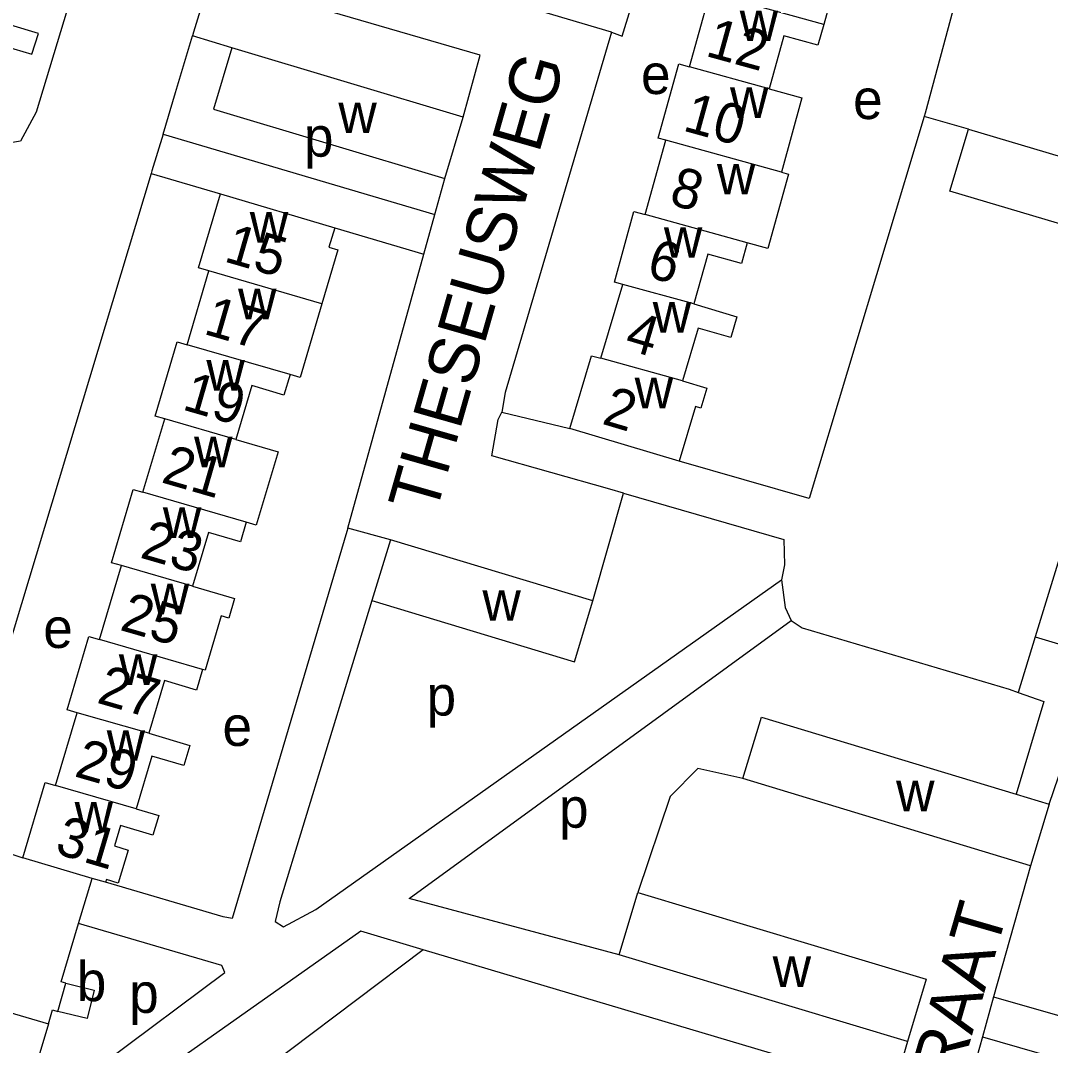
# Model space of a CAD drawing. Extents: x 161773 to 163836, y 384796 to 386521.
# Drawn here: x 162680 to 162783.7, y 386020.7 to 386123.9 of the extents above; entities that cross this region are included whole.
import ezdxf

# ---------------------------------------------------------------- set-up
doc = ezdxf.new("R2010")
doc.units = 0
for name, color, linetype in [('BLT_Basislijn', 7, 'Continuous'), ('BLT_Bebouwing', 7, 'Continuous'), ('BLT_Centroide', 7, 'Continuous'), ('BLT_Huisnummer', 7, 'Continuous'), ('BLT_Huisnummer_ tussenligend', 7, 'Continuous'), ('BLT_Onderverdeling_panden', 7, 'Continuous'), ('BLT_Straatnaam', 7, 'Continuous')]:
    doc.layers.add(name, color=color, linetype=linetype)

msp = doc.modelspace()

# ---------------------------------------------------------------- linework, layer by layer
at = {"layer": 'BLT_Basislijn'}
for p, q in [((162739.49, 386122.72), (162727.31, 386126.36)), ((162701.29, 386121.17), (162697.31, 386122.36)), ((162775.44, 386112.96), (162770.97, 386114.22)), ((162694.37, 386112.46), (162721.71, 386104.35)), ((162693.17, 386108.5), (162700.14, 386106.43)), ((162721.71, 386104.35), (162722.72, 386107.98)), ((162720.61, 386100.37), (162721.71, 386104.35)), ((162711.64, 386103.01), (162720.61, 386100.37)), ((162712.95, 386072.76), (162720.61, 386100.37)), ((162728.46, 386084.46), (162735.3, 386082.8)), ((162737.62, 386065.43), (162740.72, 386076.3)), ((162786.6, 386076.33), (162782.17, 386061.82)), ((162717.24, 386071.6), (162712.95, 386072.76)), ((162782.17, 386061.82), (162780.46, 386056.21)), ((162781.69, 386038.75), (162777.98, 386025.55)), ((162685.84, 386032.93), (162687.21, 386037.49)), ((162767.88, 386016.22), (162720.55, 386030.29)), ((162777.98, 386025.55), (162776.85, 386021.54)), ((162777.98, 386025.55), (162816.59, 386014.4)), ((162776.85, 386021.54), (162767.14, 385986.96)), ((162776.85, 386021.54), (162814.38, 386010.7)), ((162769.31, 386021.06), (162767.88, 386016.22))]:
    msp.add_line(p, q, dxfattribs=at)
for points in [[(162697.19, 386166.25), (162681.58, 386114.67), (162679.99, 386111.76), (162677.03, 386111.25), (162656.86, 386117.36)], [(162739.49, 386122.72), (162740.58, 386122.32), (162749.41, 386150.96)], [(162778.62, 386142.65), (162771.08, 386114.58), (162770.97, 386114.22)], [(162699.14, 386128.34), (162697.43, 386122.74), (162697.31, 386122.36)], [(162724.58, 386114.17), (162726.27, 386120.43), (162699.14, 386128.34)], [(162694.37, 386112.46), (162695.61, 386116.65), (162697.31, 386122.36)], [(162739.49, 386122.72), (162728.8, 386086.45), (162728.46, 386084.46)], [(162770.97, 386114.22), (162759.42, 386075.76), (162746.32, 386079.51)], [(162694.37, 386112.46), (162693.24, 386108.77), (162693.17, 386108.5)], [(162693.17, 386108.5), (162673.85, 386044.54), (162673.88, 386042.3), (162676.01, 386040.97), (162680.25, 386039.55)], [(162740.72, 386076.3), (162739.35, 386076.7), (162727.46, 386080.06), (162728.08, 386083.73), (162728.46, 386084.46)], [(162740.72, 386076.3), (162756.87, 386071.61), (162756.91, 386069.09), (162756.61, 386067.57)], [(162712.95, 386072.76), (162712.86, 386072.42), (162701.32, 386033.46), (162700.4, 386033.6), (162688.57, 386037.09)], [(162715.39, 386065.47), (162706.11, 386035.11), (162705.66, 386033.14), (162706.47, 386032.6), (162709.75, 386034.35), (162756.61, 386067.57)], [(162756.61, 386067.57), (162756.98, 386064.76), (162757.6, 386063.48)], [(162740.27, 386029.79), (162719.12, 386035.47), (162757.6, 386063.48)], [(162757.6, 386063.48), (162758.69, 386062.74), (162779.55, 386056.54), (162780.46, 386056.21)], [(162782.17, 386061.82), (162833.81, 386046.33), (162835.47, 386045.46)], [(162780.46, 386056.21), (162783.02, 386055.3), (162780.26, 386045.96)], [(162783.57, 386044.95), (162786.42, 386053.34), (162788.91, 386054.31), (162791.62, 386054.09), (162832.86, 386041.3)], [(162752.73, 386047.55), (162748.19, 386048.56), (162745.4, 386045.73), (162742.16, 386036.08)], [(162660.47, 386022.67), (162657.67, 386012.8), (162671.37, 386009.02), (162674.33, 386009.21), (162676.46, 386010), (162700.59, 386027.99), (162700.27, 386028.72), (162685.84, 386032.93)], [(162684.56, 386026.93), (162684.09, 386027.08), (162685.84, 386032.93)], [(162720.55, 386030.29), (162714.27, 386032.16), (162682.42, 386009.68), (162682.73, 386007.33), (162683.24, 386006.55), (162696.85, 386003.37)], [(162720.55, 386030.29), (162700.51, 386015.19), (162696.85, 386003.37)], [(162682.81, 386022.83), (162683.24, 386024.25), (162683.76, 386024.09)]]:
    msp.add_lwpolyline(points, dxfattribs=at)
at = {"layer": 'BLT_Bebouwing'}
for p, q in [((162747.37, 386119.24), (162749.43, 386126.68)), ((162724.58, 386114.17), (162701.29, 386121.17)), ((162722.72, 386107.98), (162724.58, 386114.17)), ((162775.44, 386112.96), (162795.86, 386106.88)), ((162742.91, 386104.35), (162744.98, 386111.84)), ((162700.14, 386106.43), (162711.64, 386103.01)), ((162696.77, 386091.25), (162698.97, 386098.68)), ((162738.44, 386089.88), (162740.66, 386097.32)), ((162692.32, 386076.39), (162694.52, 386083.77)), ((162746.32, 386079.51), (162735.3, 386082.8)), ((162717.24, 386071.6), (162715.39, 386065.47)), ((162737.62, 386065.43), (162717.24, 386071.6)), ((162687.97, 386061.55), (162690.17, 386068.99)), ((162683.54, 386046.83), (162685.72, 386054.18)), ((162781.69, 386038.75), (162752.73, 386047.55)), ((162780.26, 386045.96), (162783.57, 386044.95)), ((162783.57, 386044.95), (162781.69, 386038.75)), ((162687.21, 386037.49), (162680.25, 386039.55)), ((162688.57, 386037.09), (162687.21, 386037.49)), ((162740.27, 386029.79), (162742.16, 386036.08)), ((162769.31, 386021.06), (162740.27, 386029.79)), ((162662.33, 386028.92), (162682.81, 386022.83)), ((162683.76, 386024.09), (162684.56, 386026.93))]:
    msp.add_line(p, q, dxfattribs=at)
for points in [[(162762.95, 386131.07), (162760.87, 386123.52)], [(162674.49, 386118.8), (162677.4, 386117.93), (162678.43, 386121.32), (162681.16, 386120.5), (162681.8, 386122.61), (162679.04, 386123.45)], [(162760.87, 386123.52), (162760.29, 386121.42), (162756.86, 386122.37), (162755.39, 386117.02)], [(162701.29, 386121.17), (162699.43, 386114.98), (162722.72, 386107.98)], [(162744.98, 386111.84), (162744.21, 386112.05), (162746.27, 386119.54), (162747.37, 386119.24)], [(162755.39, 386117.02), (162758.68, 386116.12), (162756.61, 386108.63)], [(162794, 386100.64), (162773.58, 386106.72), (162775.44, 386112.96)], [(162756.61, 386108.63), (162757.33, 386108.43), (162755.26, 386100.93), (162753.17, 386101.51)], [(162698.97, 386098.68), (162697.92, 386098.98), (162700.14, 386106.43)], [(162740.66, 386097.32), (162739.81, 386097.55), (162741.77, 386104.66), (162742.91, 386104.35)], [(162711.64, 386103.01), (162711.06, 386101.06), (162711.96, 386100.79), (162710.35, 386095.36)], [(162753.17, 386101.51), (162752.6, 386099.44), (162749.19, 386100.38), (162747.79, 386095.35)], [(162710.35, 386095.36), (162708.15, 386087.94), (162707.14, 386088.24)], [(162747.79, 386095.35), (162752.14, 386094.05), (162751.52, 386091.96), (162748.24, 386092.93), (162746.65, 386087.61)], [(162694.52, 386083.77), (162693.55, 386084.05), (162695.77, 386091.54), (162696.77, 386091.25)], [(162735.3, 386082.8), (162737.48, 386090.14), (162738.44, 386089.88)], [(162707.14, 386088.24), (162706.53, 386086.17), (162703.28, 386087.14), (162701.67, 386081.7)], [(162746.65, 386087.61), (162749.09, 386086.88), (162748.49, 386084.87), (162747.96, 386085.03), (162746.32, 386079.51)], [(162701.67, 386081.7), (162705.93, 386080.44), (162703.74, 386073.06), (162702.74, 386073.36)], [(162690.17, 386068.99), (162689.16, 386069.28), (162691.35, 386076.67), (162692.32, 386076.39)], [(162702.74, 386073.36), (162702.15, 386071.38), (162698.93, 386072.34), (162697.32, 386066.92)], [(162697.32, 386066.92), (162701.56, 386065.67), (162700.97, 386063.69), (162700.2, 386063.92), (162698.58, 386058.45), (162698.34, 386058.53)], [(162715.39, 386065.47), (162735.77, 386059.3), (162737.62, 386065.43)], [(162685.72, 386054.18), (162684.71, 386054.47), (162686.9, 386061.86), (162687.97, 386061.55)], [(162698.34, 386058.53), (162697.73, 386056.45), (162694.49, 386057.41), (162692.91, 386052.1)], [(162752.73, 386047.55), (162754.61, 386053.74), (162780.26, 386045.96)], [(162692.91, 386052.1), (162697.05, 386050.87), (162696.46, 386048.86), (162693.23, 386049.81), (162691.65, 386044.49)], [(162680.25, 386039.55), (162682.49, 386047.14), (162683.54, 386046.83)], [(162691.65, 386044.49), (162693.93, 386043.82), (162693.34, 386041.85), (162690.08, 386042.81), (162689.46, 386040.75), (162690.83, 386040.34), (162689.84, 386037.01), (162688.65, 386037.36), (162688.57, 386037.09)], [(162742.16, 386036.08), (162771.2, 386027.34), (162769.31, 386021.06)], [(162684.56, 386026.93), (162687.41, 386026.24), (162686.72, 386023.38), (162683.76, 386024.09)], [(162682.81, 386022.83), (162680.95, 386016.57), (162660.47, 386022.67)]]:
    msp.add_lwpolyline(points, dxfattribs=at)
at = {"layer": 'BLT_Onderverdeling_panden'}
for p, q in [((162760.87, 386123.52), (162749.43, 386126.68)), ((162755.39, 386117.02), (162747.37, 386119.24)), ((162756.61, 386108.63), (162744.98, 386111.84)), ((162753.17, 386101.51), (162742.91, 386104.35)), ((162710.35, 386095.36), (162698.97, 386098.68)), ((162747.79, 386095.35), (162740.66, 386097.32)), ((162707.14, 386088.24), (162696.77, 386091.25)), ((162746.65, 386087.61), (162738.44, 386089.88)), ((162701.67, 386081.7), (162694.52, 386083.77)), ((162702.74, 386073.36), (162692.32, 386076.39)), ((162697.32, 386066.92), (162690.17, 386068.99)), ((162698.34, 386058.53), (162687.97, 386061.55)), ((162692.91, 386052.1), (162685.72, 386054.18)), ((162691.65, 386044.49), (162683.54, 386046.83))]:
    msp.add_line(p, q, dxfattribs=at)

# ---------------------------------------------------------------- texts
at = {"layer": 'BLT_Centroide'}
for s, p in [('w', (162752.41, 386121.84)), ('e', (162742.48, 386116.5)), ('w', (162751.44, 386114.09)), ('e', (162763.83, 386113.98)), ('w', (162712.01, 386112.56)), ('p', (162708.54, 386110.19)), ('w', (162750.12, 386106.38)), ('w', (162703.09, 386101.53)), ('w', (162744.78, 386100)), ('w', (162701.91, 386093.81)), ('w', (162743.66, 386092.47)), ('w', (162698.72, 386086.62)), ('w', (162741.84, 386084.84)), ('w', (162697.48, 386078.91)), ('w', (162694.34, 386071.78)), ('w', (162693.12, 386064.09)), ('w', (162726.51, 386063.44)), ('e', (162682.3, 386060.7)), ('w', (162689.91, 386056.97)), ('p', (162720.89, 386053.89)), ('e', (162700.34, 386050.83)), ('w', (162688.68, 386049.34)), ('w', (162768.16, 386044.25)), ('w', (162685.45, 386042.12)), ('p', (162734.22, 386042.59)), ('w', (162755.73, 386026.56)), ('b', (162685.67, 386025.12)), ('p', (162690.95, 386023.94))]:
    msp.add_text(s, height=4, dxfattribs=at).set_placement(p)
at = {"layer": 'BLT_Huisnummer'}
for s, rotation, p in [('10', 344.564, (162746.57, 386112.85)), ('15', 343.8841, (162700.37, 386099.67)), ('6', 344.5658, (162742.9, 386098.13)), ('19', 343.8879, (162696.17, 386084.75)), ('2', 343.4052, (162738.43, 386083.31)), ('23', 343.887, (162691.92, 386069.83)), ('27', 343.8874, (162687.57, 386055.21)), ('31', 343.499, (162683.34, 386040.04))]:
    msp.add_text(s, height=4, rotation=rotation, dxfattribs=at).set_placement(p)
at = {"layer": 'BLT_Huisnummer_ tussenligend'}
for s, rotation, p in [('12', 344.564, (162748.85, 386120.37)), ('8', 344.5658, (162745.18, 386105.43)), ('17', 343.8841, (162698.32, 386092.37)), ('4', 343.4052, (162740.69, 386090.85)), ('21', 343.8879, (162694.06, 386077.41)), ('25', 343.887, (162689.89, 386062.54)), ('29', 343.8874, (162685.31, 386047.8))]:
    msp.add_text(s, height=4, rotation=rotation, dxfattribs=at).set_placement(p)
at = {"layer": 'BLT_Straatnaam'}
for s, rotation, p in [('THESEUSWEG', 74.0536, (162721.78, 386074)), ('LUCRETIASTRAAT', 73.8818, (162762.9, 385977.02))]:
    msp.add_text(s, height=5, rotation=rotation, dxfattribs=at).set_placement(p)

doc.saveas('drawing.dxf')
